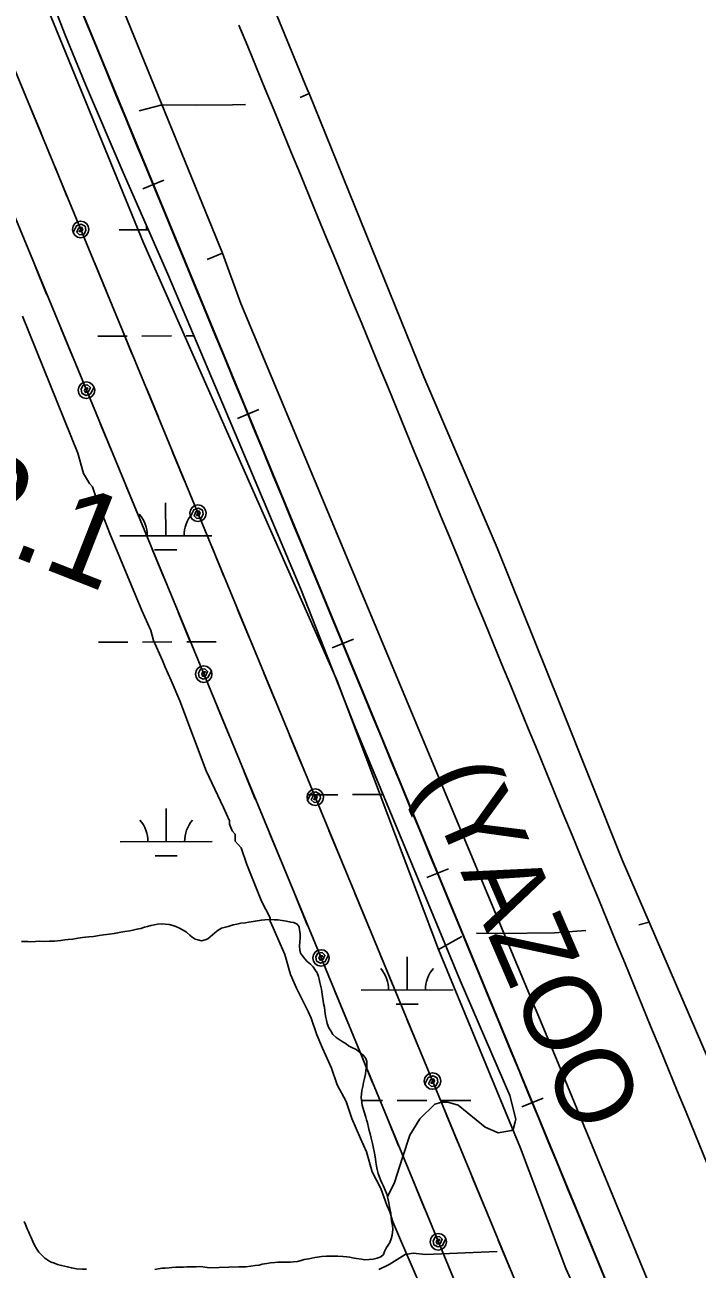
# Model space of a CAD drawing. Extents: x 3329297 to 3367176, y 649250 to 674653.
# Drawn here: x 3344034 to 3344765, y 663837 to 665190 of the extents above; entities that cross this region are included whole.
import ezdxf

# ---------------------------------------------------------------- set-up
doc = ezdxf.new("R2010")
doc.units = 0
for name, color, linetype in [('V-DTCH-CNTR', 7, 'Continuous'), ('V-RAIL-IDEN', 7, 'Continuous'), ('V-RAIL-TRAK', 7, 'Continuous'), ('V-ROAD-CNTR', 7, 'Continuous'), ('V-SURV-IDEN', 7, 'Continuous'), ('V-TOPO-SHOR', 7, 'Continuous'), ('V-UTIL-LINE', 7, 'Continuous'), ('V-WETL-SWMP', 7, 'Continuous')]:
    doc.layers.add(name, color=color, linetype=linetype)

msp = doc.modelspace()

# ---------------------------------------------------------------- linework, layer by layer
at = {"layer": 'V-DTCH-CNTR'}
msp.add_lwpolyline([(3344419.3, 663836.8), (3344430.3, 663842.5), (3344447.6, 663853.1), (3344456.6, 663854.6), (3344469.8, 663853.4), (3344547.7, 663856.4)], dxfattribs=at)
at = {"layer": 'V-RAIL-TRAK'}
for points in [[(3345872.4, 660898.3), (3345202.6, 662524.8), (3345202.6, 662524.8), (3343834.7, 665839), (3343834.7, 665839.1), (3342962.1, 667964.3), (3342962.1, 667964.3), (3342142.3, 669950.7), (3342142.3, 669950.7), (3341846.6, 670653.1)], [(3344162.5, 665012), (3344185.6, 665021.5)], [(3344265.5, 664762.4), (3344288.6, 664772)], [(3344368.5, 664512.8), (3344391.6, 664522.4)], [(3344471.5, 664263.3), (3344494.7, 664272.8)], [(3344574.6, 664013.7), (3344597.7, 664023.2)]]:
    msp.add_lwpolyline(points, dxfattribs=at)
msp.add_arc((6548955.2, 1986802.1), 3466661.3, 202.398581, 202.4578394, dxfattribs=at)
at = {"layer": 'V-ROAD-CNTR'}
msp.add_arc((64166487.8, 25668654.3), 65761050.4, 202.347120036, 202.34991448, dxfattribs=at)
at = {"layer": 'V-TOPO-SHOR'}
for p, q in [((3344333.8, 665111.4), (3344343.3, 665115.7)), ((3344701.9, 664211.8), (3344713, 664214.8))]:
    msp.add_line(p, q, dxfattribs=at)
for points in [[(3344249.2, 664942.3), (3344050.1, 665431.1), (3344030.4, 665452.2), (3343858, 665889.1), (3343769.1, 666106.8), (3343760.6, 666101.1), (3343705.5, 666251.5), (3343666, 666365.3), (3343619.4, 666450.9)], [(3343336.9, 666411), (3343473.3, 666422.5), (3343504.3, 666360.7), (3343526.8, 666349.5), (3343553.5, 666344), (3343591.5, 666334.2), (3343602.8, 666318.7), (3343793.4, 665859.4), (3343910.6, 665578.5), (3343981.3, 665398.7), (3344163.5, 664953.4), (3344373.8, 664477.2), (3344484, 664185), (3344509.3, 664199.1)], [(3344850.8, 663877.8), (3344778.3, 664063.3), (3344713, 664214.8), (3344683.8, 664282.6), (3344616.4, 664451.4), (3344547.6, 664621.7), (3344468.2, 664807.8), (3344398.7, 664978.7), (3344343.3, 665115.7), (3344341.3, 665120.6), (3344281.1, 665267.3), (3344214.9, 665421.4), (3344212.4, 665427.1), (3344208.9, 665435.4)], [(3344158.7, 665096.8), (3344183.7, 665103.4), (3344220.5, 665103.1), (3344260.1, 665103.6), (3344274.1, 665103.8)], [(3344948.5, 663256.5), (3344798.6, 663613.5), (3344612.2, 664065.8), (3344442.7, 664471.7), (3344269, 664887.5), (3344249.2, 664942.3), (3344232.4, 664935.2)], [(3344269.3, 664213.4), (3344274.1, 664213.9), (3344277.4, 664214.6), (3344280.4, 664215.1), (3344284.8, 664215.6), (3344291.5, 664216.9), (3344295.4, 664217.2), (3344300.1, 664217.7), (3344305.9, 664217), (3344309.3, 664217.1), (3344314, 664216.5), (3344318.9, 664215.6), (3344323.5, 664214.5), (3344326.8, 664214.1), (3344330.5, 664212.5), (3344332.4, 664209.5), (3344333.1, 664206), (3344333.6, 664202.3), (3344333.5, 664197.4), (3344333.3, 664193.7), (3344332.9, 664188.6), (3344333.4, 664184.2), (3344334.1, 664181), (3344336.2, 664178), (3344338.8, 664174.8), (3344341.4, 664172), (3344344.7, 664168.8), (3344347.7, 664165.9), (3344350.3, 664162.2), (3344352, 664159.4), (3344353.4, 664155.5), (3344354.2, 664152.5), (3344355.1, 664149), (3344355.6, 664146), (3344356.8, 664141.9), (3344357.3, 664138.9), (3344358.1, 664133.8), (3344358.6, 664129.1), (3344359.1, 664126.1), (3344360.1, 664122.2), (3344360.4, 664118.3), (3344360.9, 664115), (3344361.6, 664111.1), (3344362.1, 664108.1), (3344363.1, 664104.4), (3344364.8, 664099.8), (3344366.9, 664096.3), (3344369.3, 664092.4), (3344372.8, 664089.2), (3344376.1, 664086.9), (3344379.3, 664084.7), (3344383.8, 664082.2), (3344386.3, 664080.1), (3344389.1, 664078.7), (3344394.5, 664076), (3344397.5, 664074), (3344399.9, 664071.9), (3344402.9, 664069.2), (3344405, 664066.4), (3344406, 664063), (3344406.1, 664057.2), (3344405.2, 664053.7), (3344404.6, 664049.5), (3344403.5, 664044.8), (3344402.6, 664040.4), (3344401.7, 664036), (3344400.8, 664031.6), (3344400.2, 664027.7), (3344399.8, 664024.4), (3344400.3, 664020.9), (3344401.2, 664015.8), (3344402.7, 664009.4), (3344405.1, 664002.7), (3344405.8, 663999.7), (3344406.8, 663996.4), (3344408, 663991.4), (3344408.8, 663987.9), (3344409.7, 663984.4), (3344410.7, 663979.6), (3344412.2, 663974), (3344412.9, 663970.3), (3344414.1, 663965.2), (3344414.7, 663961.5), (3344415.4, 663956.9), (3344415.9, 663953.7), (3344416.7, 663949.3), (3344417.4, 663945.8), (3344418.6, 663941.4), (3344420, 663937.5), (3344421, 663934.5), (3344422.4, 663931.3), (3344424.1, 663927.6), (3344426, 663923.2), (3344427.7, 663918.8), (3344428.5, 663916), (3344429.9, 663909.3), (3344430.9, 663904.9), (3344431.4, 663901.5), (3344432.1, 663898.2), (3344432.6, 663893.1), (3344433.4, 663887.6)], [(3344030.8, 664193.6), (3344034.7, 664193.6), (3344037.7, 664193.6), (3344040.7, 664193.4), (3344046.1, 664193.5), (3344049.8, 664193.8), (3344054.2, 664193.6), (3344061.1, 664193.9), (3344066.5, 664194), (3344073.6, 664194.8), (3344077.8, 664195.5), (3344081.5, 664195.8), (3344086.4, 664196.3), (3344091.9, 664197.1), (3344097, 664197.8), (3344100.5, 664198.3), (3344104, 664198.8), (3344109.1, 664199.1), (3344115.1, 664200.1), (3344119.9, 664200.7), (3344123.2, 664201.2), (3344126.2, 664201.7), (3344131.5, 664202.4), (3344135.2, 664202.9), (3344138.7, 664203.7), (3344143.1, 664204.4), (3344148.4, 664205.2), (3344151.9, 664205.9), (3344156.2, 664206.9), (3344160.4, 664207.9), (3344164.6, 664209.1), (3344167.8, 664210), (3344171.3, 664211), (3344175.4, 664211.8), (3344178.7, 664212.5), (3344183.3, 664212.8), (3344187, 664212.6), (3344191.2, 664212.2), (3344195.1, 664211.1), (3344198.4, 664210), (3344201.9, 664208.4), (3344206.3, 664206.1), (3344210.1, 664203.6), (3344213.6, 664200.6), (3344216.2, 664198.3), (3344219.4, 664196.3), (3344222.5, 664195.4), (3344226.4, 664194.5), (3344230.3, 664195.3), (3344233.3, 664196.5), (3344235.9, 664198.6), (3344238.4, 664200.7), (3344240.9, 664203.1), (3344244.6, 664205.9), (3344248.3, 664208), (3344252.4, 664209.2), (3344255.4, 664210), (3344260.7, 664211.6), (3344264.7, 664212.4), (3344269.3, 664213.4)], [(3344525.4, 664202.7), (3344551.1, 664202.3), (3344610.2, 664203), (3344644.3, 664205.5)], [(3344484, 664185), (3344573, 663968.7), (3344622.4, 663838.1), (3344678.9, 663713.1), (3344741.1, 663559.9), (3344751.1, 663533)], [(3344101.4, 663837.2), (3344096.7, 663837.4), (3344090.7, 663837.8), (3344085.1, 663838.6), (3344080.7, 663839.7), (3344074.4, 663841.3), (3344070, 663842.4), (3344066.5, 663843.7), (3344063, 663844.9), (3344060.5, 663846.5), (3344056, 663849.2), (3344053, 663852.4), (3344049.7, 663855.8), (3344047.3, 663859), (3344045, 663863.4), (3344043.1, 663867.3), (3344041.2, 663871.7), (3344040, 663874.7), (3344038.5, 663878.2), (3344037.1, 663881.2), (3344035, 663886), (3344033.8, 663889)], [(3344433.4, 663887.6), (3344433.9, 663884.6), (3344434.2, 663880.4), (3344433.6, 663874.4), (3344432.4, 663870.2), (3344431.1, 663866.2), (3344429.3, 663863.4), (3344427.5, 663860.9), (3344425.4, 663856.4), (3344424.1, 663853.4), (3344421.3, 663850.8), (3344417.2, 663849.4), (3344413, 663848.2), (3344408.8, 663847.7), (3344404, 663847.6), (3344400.3, 663848), (3344394.9, 663848.9), (3344390.7, 663849.5), (3344387.7, 663850.2), (3344384.5, 663850.6), (3344380.3, 663851.2), (3344374.7, 663851.4), (3344370.3, 663851.6), (3344365.9, 663851.5), (3344362.2, 663851.5), (3344356.9, 663851), (3344352.5, 663850.4), (3344349.5, 663849.9), (3344343.2, 663848.7), (3344338.1, 663847.7), (3344334.9, 663846.8), (3344330.8, 663845.8), (3344326.4, 663845.3), (3344322.9, 663845), (3344318, 663844.9), (3344314.3, 663844.9), (3344309.4, 663844.8), (3344306.2, 663844.6), (3344301.3, 663844), (3344297.4, 663843.5), (3344292.3, 663842.8), (3344289.1, 663841.8), (3344284.9, 663841.3), (3344280.1, 663840.5), (3344274.7, 663840), (3344271, 663840), (3344267.1, 663839.7), (3344234.9, 663838.6)], [(3344234.9, 663838.6), (3344227.7, 663839.9), (3344224, 663840.1), (3344220.7, 663840), (3344215.2, 663840), (3344210.5, 663839.7), (3344206.8, 663839.6), (3344202, 663839.4), (3344198.5, 663839.3), (3344194.1, 663839), (3344191.1, 663838.8), (3344186.9, 663838.2), (3344183.7, 663838.2), (3344179.3, 663837.5), (3344175.6, 663837)]]:
    msp.add_lwpolyline(points, dxfattribs=at)
at = {"layer": 'V-UTIL-LINE'}
for points in [[(3345932.1, 660508.5), (3345266.9, 662132.1), (3344424.6, 664170), (3343419, 666605.5), (3342586.6, 668628.9), (3341907.6, 670274.6), (3341535.6, 671146.2)], [(3341480.8, 671097), (3341874.4, 670184.1), (3342489.4, 668700.6), (3343600.8, 666004.9), (3344292.6, 664330.1), (3345012, 662588.2), (3345711.5, 660882.6)], [(3344052, 665072.5), (3344039, 665103.9)], [(3344080.2, 665004.1), (3344067.3, 665035.5)], [(3344095.1, 664968), (3344093.6, 664965.6), (3344095.9, 664965.7), (3344097.3, 664968), (3344095.9, 664970.6), (3344092.7, 664969.4), (3344090.8, 664965.1), (3344093.9, 664962.2), (3344098.8, 664962.8), (3344100.7, 664967), (3344100, 664971.4), (3344095.7, 664973.6), (3344090.5, 664971.8), (3344086.8, 664964.6), (3344088.8, 664961.6), (3344091.7, 664959.7), (3344095.1, 664959), (3344098.6, 664959.7), (3344101.5, 664961.6), (3344103.4, 664964.5), (3344104.1, 664968), (3344103.4, 664971.4), (3344101.5, 664974.4), (3344098.6, 664976.3), (3344095.1, 664977), (3344091.7, 664976.3), (3344088.8, 664974.4), (3344086.8, 664971.4), (3344086.1, 664968), (3344086.8, 664964.6)], [(3344045.2, 664929), (3344058.1, 664897.6)], [(3344123, 664900.5), (3344110, 664932)], [(3344161.7, 664553.7), (3344126.8, 664637.3), (3344114.2, 664670), (3344107.8, 664688.1), (3344104.6, 664691.8), (3344098.3, 664702.7), (3344092, 664724.5), (3344031.8, 664873.5)], [(3344073.4, 664860.6), (3344086.4, 664829.2)], [(3344151.2, 664832.1), (3344138.2, 664863.6)], [(3344101.3, 664793.1), (3344102.8, 664795.6), (3344100.5, 664795.5), (3344099.1, 664793.1), (3344100.5, 664790.6), (3344103.7, 664791.7), (3344105.6, 664796), (3344102.5, 664798.9), (3344097.6, 664798.3), (3344095.7, 664794.2), (3344096.4, 664789.8), (3344100.7, 664787.5), (3344105.9, 664789.3), (3344109.6, 664796.6), (3344107.6, 664799.5), (3344104.7, 664801.5), (3344101.3, 664802.1), (3344097.8, 664801.5), (3344094.9, 664799.5), (3344093, 664796.6), (3344092.3, 664793.2), (3344093, 664789.7), (3344094.9, 664786.8), (3344097.8, 664784.8), (3344101.3, 664784.1), (3344104.7, 664784.8), (3344107.6, 664786.8), (3344109.6, 664789.7), (3344110.3, 664793.1), (3344109.6, 664796.6)], [(3344179.5, 664763.7), (3344166.5, 664795.2)], [(3344116.2, 664757.1), (3344129.2, 664725.6)], [(3344207.7, 664695.3), (3344194.7, 664726.8)], [(3344144.4, 664688.7), (3344157.4, 664657.2)], [(3344222.6, 664659.3), (3344221, 664656.9), (3344223.4, 664656.9), (3344224.8, 664659.3), (3344223.4, 664661.9), (3344220.2, 664660.7), (3344218.3, 664656.4), (3344221.4, 664653.5), (3344226.2, 664654.1), (3344228.2, 664658.2), (3344227.4, 664662.7), (3344223.2, 664664.9), (3344218, 664663.1), (3344214.3, 664655.8), (3344216.2, 664652.9), (3344219.1, 664651), (3344222.6, 664650.3), (3344226, 664651), (3344228.9, 664652.9), (3344230.9, 664655.8), (3344231.6, 664659.3), (3344230.9, 664662.7), (3344229, 664665.6), (3344226, 664667.6), (3344222.6, 664668.3), (3344219.2, 664667.6), (3344216.2, 664665.6), (3344214.3, 664662.7), (3344213.6, 664659.3), (3344214.3, 664655.8)], [(3344172.7, 664620.3), (3344185.7, 664588.9)], [(3344250.4, 664591.8), (3344237.5, 664623.2)], [(3344462.7, 663823.2), (3344453.2, 663845), (3344443.7, 663866.8), (3344434.2, 663888.6), (3344431, 663899.5), (3344427.8, 663906.8), (3344421.5, 663925), (3344412, 663943.1), (3344405.7, 663964.9), (3344399.3, 663979.5), (3344389.8, 664001.3), (3344383.5, 664019.5), (3344374, 664037.6), (3344367.6, 664055.8), (3344358.1, 664077.6), (3344351.8, 664092.1), (3344345.5, 664110.3), (3344342.3, 664117.6), (3344329.6, 664143), (3344323.3, 664157.6), (3344317, 664179.4), (3344304.3, 664208.4), (3344301.1, 664215.7), (3344301.1, 664219.3), (3344291.6, 664237.5), (3344275.7, 664277.5), (3344269.4, 664295.6), (3344263.1, 664302.9), (3344263.1, 664310.2), (3344259.9, 664313.8), (3344256.7, 664321.1), (3344256.7, 664324.7), (3344250.4, 664339.2), (3344231.4, 664379.2), (3344202.9, 664455.5), (3344193.4, 664477.4), (3344190.2, 664484.6), (3344187, 664491.9), (3344183.9, 664499.2), (3344180.7, 664506.4), (3344177.5, 664513.7), (3344174.4, 664521), (3344171.2, 664531.9), (3344161.7, 664553.7)], [(3344200.9, 664551.9), (3344213.9, 664520.5)], [(3344278.7, 664523.4), (3344265.7, 664554.8)], [(3344228.8, 664484.4), (3344230.4, 664486.9), (3344228, 664486.8), (3344226.6, 664484.4), (3344228, 664481.9), (3344231.2, 664483), (3344233.1, 664487.3), (3344230, 664490.2), (3344225.2, 664489.6), (3344223.2, 664485.5), (3344224, 664481.1), (3344228.2, 664478.8), (3344233.4, 664480.6), (3344237.1, 664487.9), (3344235.2, 664490.8), (3344232.2, 664492.8), (3344228.8, 664493.4), (3344225.4, 664492.8), (3344222.4, 664490.8), (3344220.5, 664487.9), (3344219.8, 664484.5), (3344220.5, 664481), (3344222.4, 664478.1), (3344225.3, 664476.1), (3344228.8, 664475.4), (3344232.2, 664476.1), (3344235.2, 664478.1), (3344237.1, 664481), (3344237.8, 664484.4), (3344237.1, 664487.9)], [(3344306.9, 664455), (3344293.9, 664486.4)], [(3344243.7, 664448.4), (3344256.7, 664416.9)], [(3344335.2, 664386.6), (3344322.2, 664418)], [(3344271.9, 664380), (3344284.9, 664348.5)], [(3344350.1, 664350.6), (3344348.5, 664348.1), (3344350.8, 664348.2), (3344352.3, 664350.6), (3344350.8, 664353.1), (3344347.6, 664352), (3344345.7, 664347.7), (3344348.9, 664344.8), (3344353.7, 664345.4), (3344355.7, 664349.5), (3344354.9, 664353.9), (3344350.6, 664356.2), (3344345.4, 664354.4), (3344341.7, 664347.1), (3344343.7, 664344.2), (3344346.6, 664342.2), (3344350, 664341.6), (3344353.5, 664342.2), (3344356.4, 664344.2), (3344358.4, 664347.1), (3344359.1, 664350.5), (3344358.4, 664354), (3344356.4, 664356.9), (3344353.5, 664358.9), (3344350.1, 664359.6), (3344346.6, 664358.9), (3344343.7, 664356.9), (3344341.7, 664354), (3344341.1, 664350.6), (3344341.7, 664347.1)], [(3344377.9, 664283.1), (3344364.9, 664314.5)], [(3344300.2, 664311.6), (3344313.2, 664280.2)], [(3344406.2, 664214.7), (3344393.2, 664246.1)], [(3344328.5, 664243.2), (3344341.4, 664211.8)], [(3344356.3, 664175.7), (3344357.9, 664178.2), (3344355.5, 664178.1), (3344354.1, 664175.7), (3344355.5, 664173.2), (3344358.7, 664174.3), (3344360.6, 664178.6), (3344357.5, 664181.5), (3344352.7, 664180.9), (3344350.7, 664176.8), (3344351.5, 664172.4), (3344355.7, 664170.1), (3344360.9, 664171.9), (3344364.6, 664179.2), (3344362.7, 664182.1), (3344359.8, 664184.1), (3344356.3, 664184.7), (3344352.9, 664184.1), (3344349.9, 664182.1), (3344348, 664179.2), (3344347.3, 664175.8), (3344348, 664172.3), (3344349.9, 664169.4), (3344352.9, 664167.4), (3344356.3, 664166.7), (3344359.7, 664167.4), (3344362.7, 664169.4), (3344364.6, 664172.3), (3344365.3, 664175.7), (3344364.6, 664179.2)], [(3344434.4, 664146.3), (3344424.6, 664170), (3344421.4, 664177.7)], [(3344371.2, 664139.7), (3344384.2, 664108.2)], [(3344462.7, 664077.9), (3344449.7, 664109.3)], [(3344399.5, 664071.3), (3344412.4, 664039.8)], [(3344477.6, 664041.9), (3344476, 664039.4), (3344478.3, 664039.5), (3344479.8, 664041.9), (3344478.4, 664044.4), (3344475.2, 664043.3), (3344473.3, 664039), (3344476.4, 664036.1), (3344481.2, 664036.7), (3344483.2, 664040.8), (3344482.4, 664045.2), (3344478.1, 664047.5), (3344472.9, 664045.7), (3344469.2, 664038.4), (3344471.2, 664035.5), (3344474.1, 664033.5), (3344477.6, 664032.9), (3344481, 664033.5), (3344483.9, 664035.5), (3344485.9, 664038.4), (3344486.6, 664041.9), (3344485.9, 664045.3), (3344483.9, 664048.2), (3344481, 664050.2), (3344477.6, 664050.9), (3344474.1, 664050.2), (3344471.2, 664048.2), (3344469.3, 664045.3), (3344468.6, 664041.9), (3344469.2, 664038.4)], [(3344427.7, 664002.9), (3344440.7, 663971.4)], [(3344505.4, 663974.4), (3344492.5, 664005.8)], [(3344456, 663934.5), (3344468.9, 663903.1)], [(3344533.7, 663906), (3344520.7, 663937.4)], [(3344483.8, 663867), (3344485.4, 663869.5), (3344483, 663869.4), (3344481.6, 663867), (3344483, 663864.5), (3344486.2, 663865.6), (3344488.1, 663869.9), (3344485, 663872.8), (3344480.2, 663872.2), (3344478.2, 663868.1), (3344479, 663863.7), (3344483.2, 663861.4), (3344488.4, 663863.2), (3344492.1, 663870.5), (3344490.2, 663873.4), (3344487.3, 663875.4), (3344483.8, 663876), (3344480.4, 663875.4), (3344477.5, 663873.4), (3344475.5, 663870.5), (3344474.8, 663867), (3344475.5, 663863.6), (3344477.4, 663860.7), (3344480.4, 663858.7), (3344483.8, 663858), (3344487.2, 663858.7), (3344490.2, 663860.7), (3344492.1, 663863.6), (3344492.8, 663867), (3344492.1, 663870.5)], [(3344562, 663837.6), (3344549, 663869)]]:
    msp.add_lwpolyline(points, dxfattribs=at)
at = {"layer": 'V-WETL-SWMP'}
for p, q in [((3344136.8, 664967.4), (3344168.5, 664967.4)), ((3344174.9, 664952), (3344175.3, 664952)), ((3344113.7, 664851.9), (3344145.7, 664852)), ((3344161.7, 664852), (3344193.7, 664852.1)), ((3344209.7, 664852.1), (3344218.1, 664852.1)), ((3344187.5, 664634.8), (3344187.4, 664670.8)), ((3344137.5, 664634.7), (3344237.5, 664634.9)), ((3344175.5, 664619.4), (3344199.5, 664619.4)), ((3344114.3, 664519.2), (3344146.3, 664519.3)), ((3344162.3, 664519.3), (3344194.3, 664519.4)), ((3344210.3, 664519.4), (3344242.3, 664519.5)), ((3344342.6, 664353.2), (3344374.6, 664353.2)), ((3344390.6, 664353.3), (3344422.6, 664353.3)), ((3344188.1, 664302.1), (3344188, 664338.1)), ((3344138.1, 664302), (3344238.1, 664302.2)), ((3344176.1, 664286.7), (3344200.1, 664286.7)), ((3344449.8, 664140.8), (3344449.8, 664176.8)), ((3344399.8, 664140.7), (3344499.8, 664140.9)), ((3344437.9, 664125.3), (3344461.9, 664125.4)), ((3344400.3, 664020.6), (3344423.2, 664020.6)), ((3344439.2, 664020.7), (3344471.2, 664020.7)), ((3344487.2, 664020.8), (3344519.2, 664020.8))]:
    msp.add_line(p, q, dxfattribs=at)
for points in [[(3344047.2, 665260.5), (3344078, 665180.2), (3344100.3, 665125.5), (3344141.1, 665030), (3344189.7, 664919.3), (3344253.4, 664768.5), (3344334.3, 664576.9), (3344393.1, 664427.4), (3344461.9, 664261.3), (3344507.7, 664151.3), (3344561.4, 664026.1), (3344568, 664000.4), (3344567.3, 663997.6), (3344565.3, 663989.3), (3344563.2, 663987.9), (3344548.7, 663985.6), (3344534.7, 663991.7), (3344505.2, 664015.7), (3344494, 664019), (3344487.8, 664018.9), (3344480.1, 664016.8), (3344463.6, 664000.6), (3344452.7, 663983.1), (3344444.7, 663958.6), (3344436, 663931.4), (3344428.5, 663916), (3344427.7, 663918.8), (3344426, 663923.2)], [(3344426, 663923.2), (3344424.1, 663927.6), (3344422.4, 663931.3), (3344421, 663934.5), (3344420, 663937.5), (3344418.6, 663941.4), (3344417.4, 663945.8), (3344416.7, 663949.3), (3344415.9, 663953.7), (3344415.4, 663956.9), (3344414.7, 663961.5), (3344414.1, 663965.2), (3344412.9, 663970.3), (3344412.2, 663974), (3344410.7, 663979.6), (3344409.7, 663984.4), (3344408.8, 663987.9), (3344408, 663991.4), (3344406.8, 663996.4), (3344405.9, 663999.7), (3344405.1, 664002.7), (3344402.7, 664009.4), (3344401.2, 664015.8), (3344400.3, 664020.9), (3344399.8, 664024.4), (3344400.2, 664027.7), (3344400.8, 664031.6), (3344401.7, 664036), (3344402.6, 664040.4), (3344403.5, 664044.8), (3344404.6, 664049.5), (3344405.2, 664053.7), (3344406.1, 664057.2), (3344406, 664063), (3344405, 664066.4), (3344402.9, 664069.2), (3344399.9, 664071.9), (3344397.5, 664074), (3344394.5, 664076), (3344389.1, 664078.7), (3344386.3, 664080.1), (3344383.8, 664082.2), (3344379.3, 664084.7), (3344376.1, 664086.9), (3344372.8, 664089.2), (3344369.3, 664092.4), (3344366.9, 664096.3), (3344364.8, 664099.8), (3344363.1, 664104.4), (3344362.1, 664108.1), (3344361.6, 664111.1), (3344360.9, 664115), (3344360.4, 664118.3), (3344360.1, 664122.2), (3344359.1, 664126.1), (3344358.6, 664129.1), (3344358.1, 664133.8), (3344357.3, 664138.9), (3344356.8, 664141.9), (3344355.6, 664146), (3344355.1, 664149), (3344354.2, 664152.5), (3344353.4, 664155.5), (3344352, 664159.4), (3344350.3, 664162.2), (3344347.7, 664165.9), (3344344.7, 664168.8), (3344341.4, 664172), (3344338.8, 664174.8), (3344336.2, 664178), (3344334.1, 664181), (3344333.4, 664184.2), (3344332.9, 664188.6), (3344333.3, 664193.7), (3344333.5, 664197.4), (3344333.6, 664202.3), (3344333.1, 664206), (3344332.4, 664209.5), (3344330.5, 664212.5), (3344326.8, 664214.1), (3344323.5, 664214.5), (3344318.9, 664215.6), (3344314, 664216.5), (3344309.3, 664217.1), (3344305.9, 664217), (3344300.1, 664217.7), (3344295.4, 664217.2), (3344291.5, 664216.9), (3344284.8, 664215.6), (3344280.4, 664215.1), (3344277.4, 664214.6), (3344274.1, 664213.9), (3344269.3, 664213.4)], [(3344269.3, 664213.4), (3344264.7, 664212.4), (3344260.7, 664211.6), (3344255.4, 664209.9), (3344252.4, 664209.2), (3344248.3, 664208), (3344244.6, 664205.9), (3344240.9, 664203.1), (3344238.4, 664200.7), (3344235.9, 664198.6), (3344233.3, 664196.5), (3344230.3, 664195.3), (3344226.4, 664194.5), (3344222.5, 664195.4), (3344219.4, 664196.3), (3344216.2, 664198.3), (3344213.6, 664200.6), (3344210.1, 664203.6), (3344206.3, 664206.1), (3344201.9, 664208.4), (3344198.4, 664210), (3344195.1, 664211.1), (3344191.2, 664212.2), (3344187, 664212.6), (3344183.3, 664212.8), (3344178.7, 664212.5), (3344175.4, 664211.8), (3344171.3, 664211), (3344167.8, 664210), (3344164.6, 664209.1), (3344160.4, 664207.9), (3344156.2, 664206.9), (3344151.9, 664205.9), (3344148.4, 664205.2), (3344143.1, 664204.4), (3344138.7, 664203.7), (3344135.2, 664202.9), (3344131.5, 664202.4), (3344126.2, 664201.7), (3344123.2, 664201.2), (3344119.9, 664200.7), (3344115.1, 664200.1), (3344109.1, 664199.1), (3344104, 664198.8), (3344100.5, 664198.3), (3344097, 664197.8), (3344091.9, 664197.1), (3344086.4, 664196.3), (3344081.5, 664195.8), (3344077.8, 664195.5), (3344073.6, 664194.8), (3344066.5, 664194), (3344061.1, 664193.9), (3344054.2, 664193.6), (3344049.8, 664193.8), (3344046.1, 664193.5), (3344040.7, 664193.4), (3344037.7, 664193.6), (3344034.7, 664193.6), (3344030.8, 664193.6)]]:
    msp.add_lwpolyline(points, dxfattribs=at)
for centre, start, end in [((3344131.6, 664967.9), 359.3365, 6.4947), ((3344132.2, 664635.2), 359.3365, 40.8801), ((3344242.7, 664635.4), 139.3365, 180.8801), ((3344132.9, 664302.5), 359.3365, 40.8801), ((3344243.3, 664302.7), 139.3365, 180.8801), ((3344394.6, 664141.1), 359.3365, 40.8801), ((3344505.1, 664141.3), 139.3365, 180.8801)]:
    msp.add_arc(centre, 35.2, start, end, dxfattribs=at)

# ---------------------------------------------------------------- texts
at = {"layer": 'V-RAIL-IDEN'}
msp.add_text('(YAZOO', height=83, rotation=293.3326, dxfattribs=at).set_placement((3344463.6, 664371.4))
at = {"layer": 'V-SURV-IDEN'}
msp.add_text('684+82.1', height=100, rotation=338.5856, dxfattribs=at).set_placement((3343597.3, 664778.6))

doc.saveas('drawing.dxf')
